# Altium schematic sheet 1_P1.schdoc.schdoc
size 309 x 223 mm; Symbol: Sheet-Symbol_A4; Device: Sheet-Symbol_A4; @Page Name: P1; @Create Date: 2023-04-29; @Page Count: 1; @Page No: 1; @Project Name: dc_to_dc; @Schematic Name: Schematic1; @Update Date: 2024-04-25; Company: 嘉立创EDA; Page Size: A4; Version: V1.0
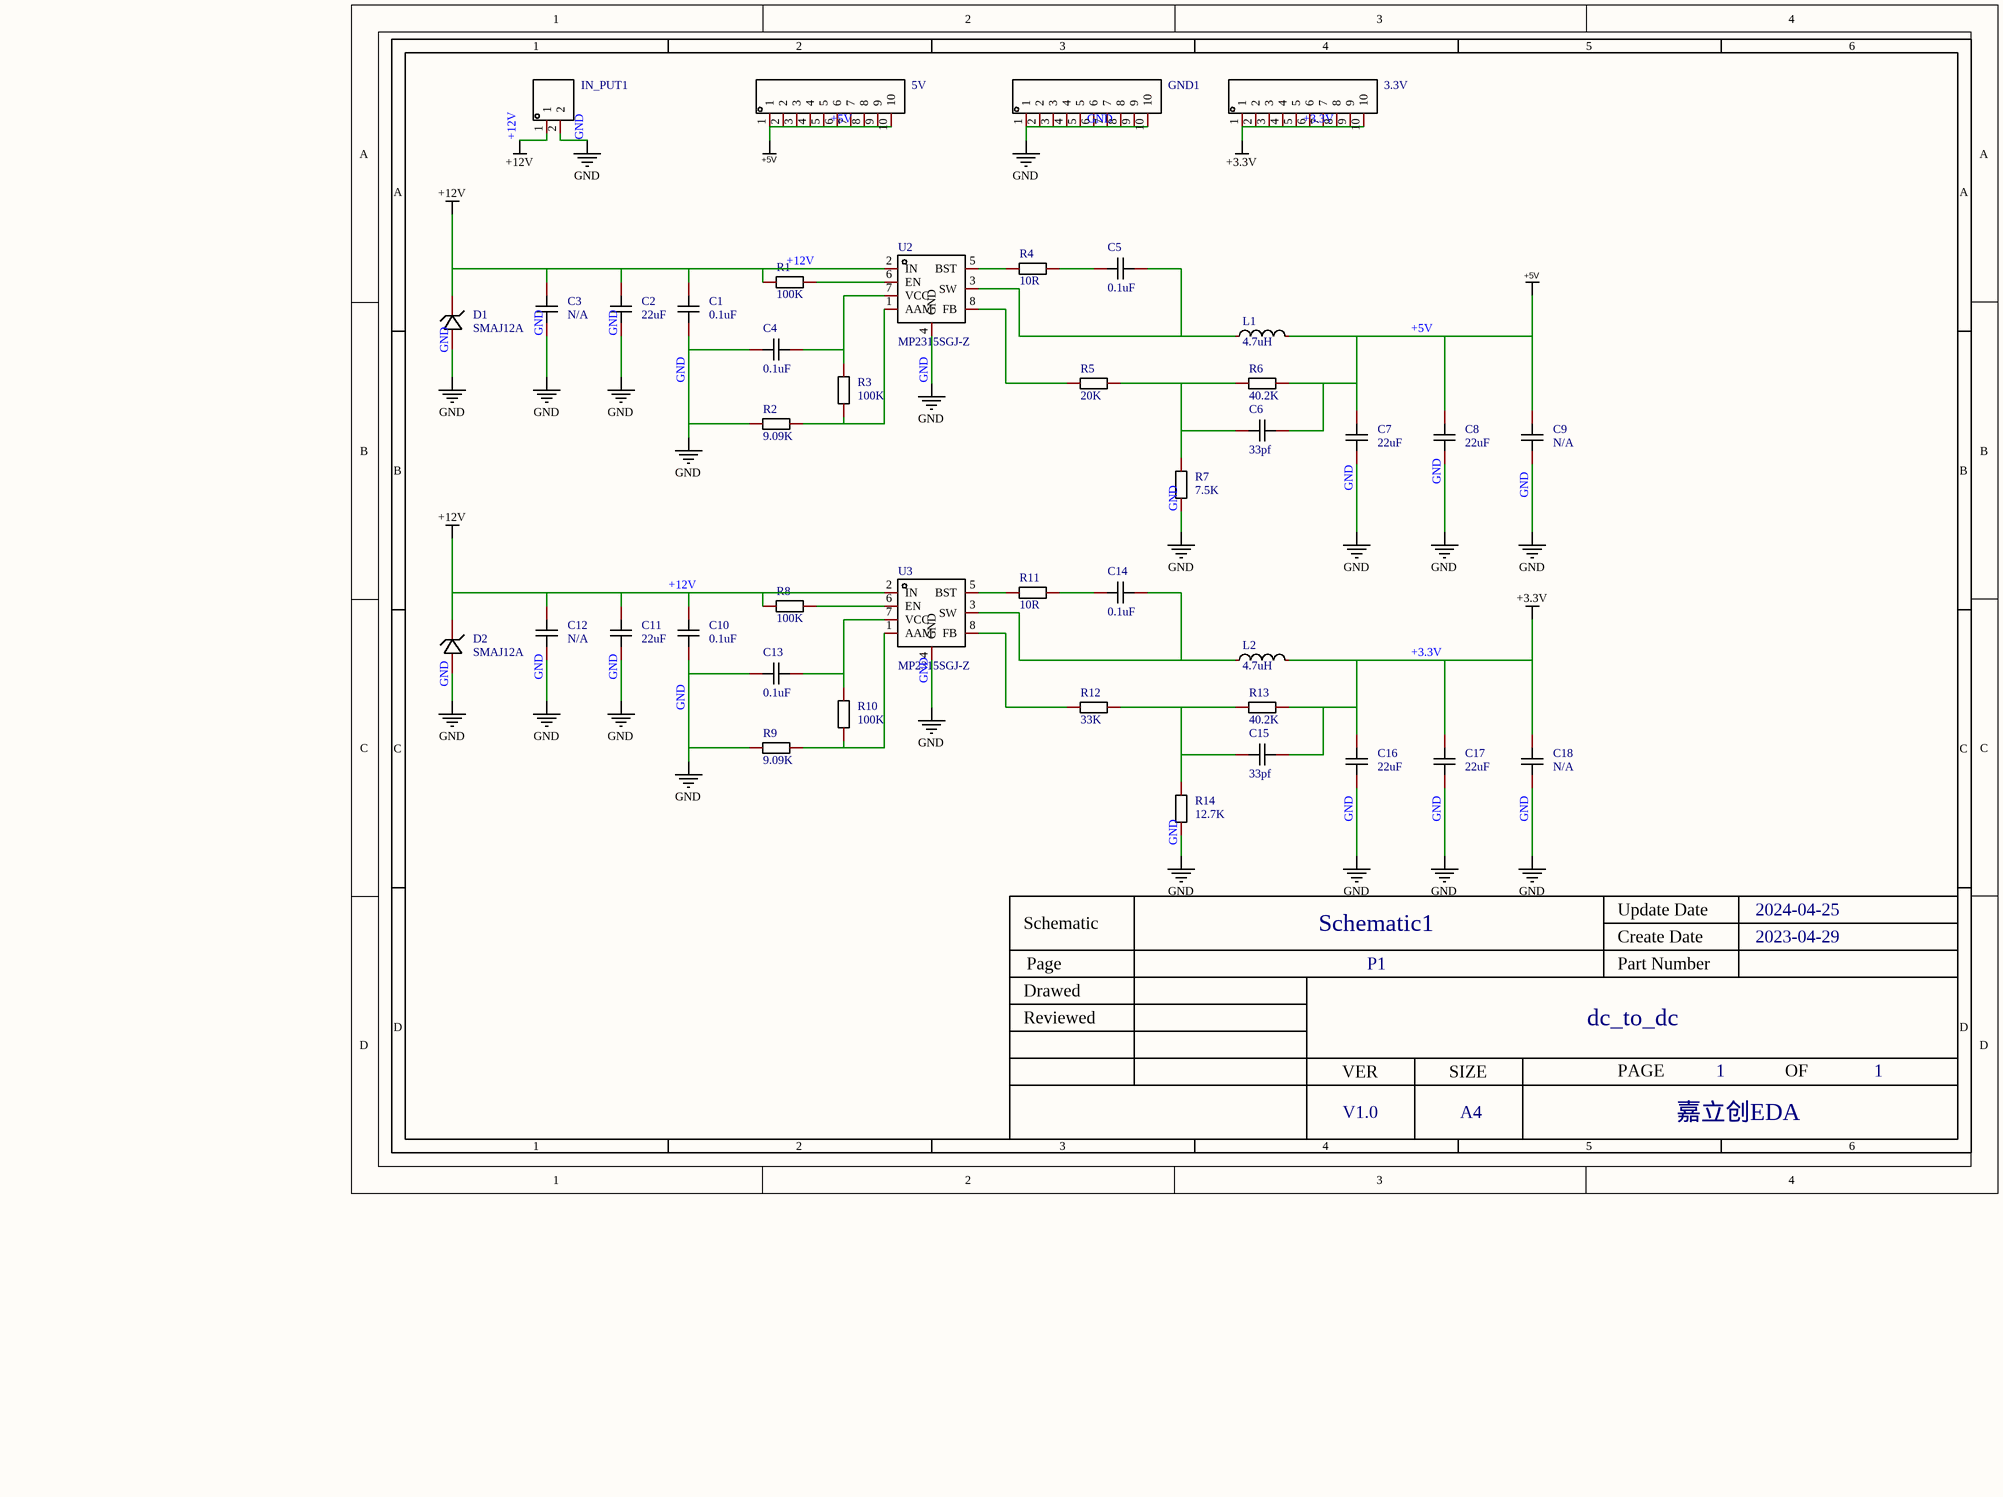
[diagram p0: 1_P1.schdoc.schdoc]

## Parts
3.3V  HDR-M_2.54_1x10P  [HDR-TH_10P-P2.54-V-M-1]  (value not drawn)
5V  HDR-M_2.54_1x10P  [HDR-TH_10P-P2.54-V-M-1]  (value not drawn)
C1  0.1uF  [C0603]
C2  22uF  [C0603]
C3  N/A  [C0603]
C4  0.1uF  [C0603]
C5  0.1uF  [C0603]
C6  33pf  [C0603]
C7  22uF  [C0603]
C8  22uF  [C0603]
C9  N/A  [C0603]
C10  0.1uF  [C0603]
C11  22uF  [C0603]
C12  N/A  [C0603]
C13  0.1uF  [C0603]
C14  0.1uF  [C0603]
C15  33pf  [C0603]
C16  22uF  [C0603]
C17  22uF  [C0603]
C18  N/A  [C0603]
D1  SMAJ12A  [SMA_L4.4-W2.8-LS5.4-RD]
D2  SMAJ12A  [SMA_L4.4-W2.8-LS5.4-RD]
GND1  HDR-M_2.54_1x10P  [HDR-TH_10P-P2.54-V-M-1]  (value not drawn)
IN_PUT1  HDR-M_2.54_1x2P  [HDR-TH_2P-P2.54-V-M-1]  (value not drawn)
L1  4.7uH  [IND-SMD_L7.3-W6.6_MHCI06030]
L2  4.7uH  [IND-SMD_L7.3-W6.6_MHCI06030]
R1  100K  [R0603]
R2  9.09K  [R0603]
R3  100K  [R0603]
R4  10R  [R0603]
R5  20K  [R0603]
R6  40.2K  [R0603]
R7  7.5K  [R0603]
R8  100K  [R0603]
R9  9.09K  [R0603]
R10  100K  [R0603]
R11  10R  [R0603]
R12  33K  [R0603]
R13  40.2K  [R0603]
R14  12.7K  [R0603]
U2  MP2315SGJ-Z  [TSOT-23-8_L2.9-W1.6-P0.65-LS2.8-BL]
U3  MP2315SGJ-Z  [TSOT-23-8_L2.9-W1.6-P0.65-LS2.8-BL]

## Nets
+3.3V: 3.3V.1 3.3V.2 3.3V.3 3.3V.4 3.3V.5 3.3V.6 3.3V.7 3.3V.8 3.3V.9 3.3V.10 C15.2 C16.1 C17.1 C18.1 L2.2 R13.2
+5V: 5V.1 5V.2 5V.3 5V.4 5V.5 5V.6 5V.7 5V.8 5V.9 5V.10 C6.2 C7.1 C8.1 C9.1 L1.2 R6.2
+12V: C1.2 C2.2 C3.2 C10.2 C11.2 C12.2 D1.1 D2.1 IN_PUT1.1 R1.1 R8.1 U2.2(IN) U3.2(IN)
GND: C1.1 C2.1 C3.1 C4.1 C7.2 C8.2 C9.2 C10.1 C11.1 C12.1 C13.1 C16.2 C17.2 C18.2 D1.2 D2.2 GND1.1 GND1.2 GND1.3 GND1.4 GND1.5 GND1.6 GND1.7 GND1.8 GND1.9 GND1.10 IN_PUT1.2 R2.1 R7.1 R9.1 R14.1 U2.4(GND) U3.4(GND)
NetC4_2: C4.2 R3.2 U2.7(VCC)
NetC5_1: C5.1 R4.2
NetC5_2: C5.2 L1.1 U2.3(SW)
NetC6_1: C6.1 R5.2 R6.1 R7.2
NetC13_2: C13.2 R10.2 U3.7(VCC)
NetC14_1: C14.1 R11.2
NetC14_2: C14.2 L2.1 U3.3(SW)
NetC15_1: C15.1 R12.2 R13.1 R14.2
NetR1_2: R1.2 U2.6(EN)
NetR2_2: R2.2 R3.1 U2.1(AAM)
NetR4_1: R4.1 U2.5(BST)
NetR5_1: R5.1 U2.8(FB)
NetR8_2: R8.2 U3.6(EN)
NetR9_2: R9.2 R10.1 U3.1(AAM)
NetR11_1: R11.1 U3.5(BST)
NetR12_1: R12.1 U3.8(FB)

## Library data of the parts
3.3V 5V GND1 = HDR-M_2.54_1x10P: Symbol: Header-Male-2.54_1x10; Convert to PCB: yes
C1-C18 = CAP_0603: Symbol: CapAcitance; Convert to PCB: yes
D1 D2 = SMAJ12A_C220440: 极性:Unidirectional;峰值脉冲电流（10/1000us）:20.1A;箝位电压:19.9V;击穿电压（最小值）:13.3V;反向关断电压（典型值）:12V;; Add into BOM: yes
IN_PUT1 = HDR-M_2.54_1x2P: Symbol: 210S-1*2P L=11.6MMGold-plated black; Convert to PCB: yes
L1 L2 = MHCI06030-4R7M-R8: 电感值:4.7uH;精度:±20%;额定电流:5.5A;饱和电流(Isat):9A;; Manufacturer: chilisin(奇力新); Add into BOM: yes; Tolerance: ±20%; Rated Current: 5.5A; Saturation Current (Isat): 9A; DC Resistance (DCR): 40mΩ
R1-R14 = Res_0603: Symbol: 电阻; Convert to PCB: yes
U2 U3 = MP2315SGJ-Z: Add into BOM: yes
